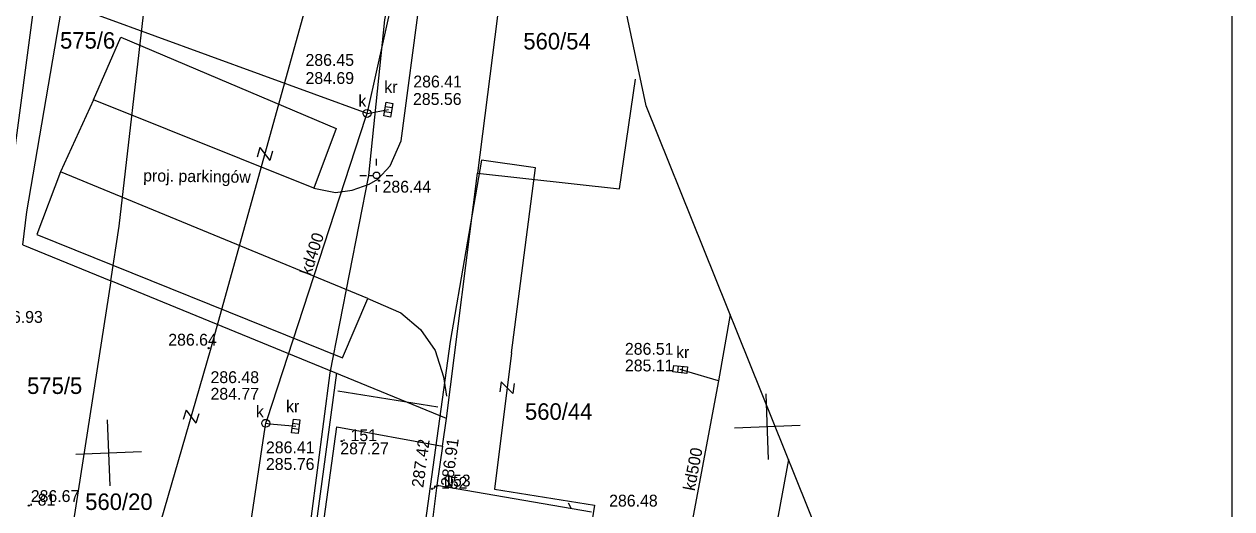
# Model space of a CAD drawing. Extents: x 4632591 to 4651936, y 5351032 to 5369988.
# Drawn here: x 4642775.6 to 4642867.2, y 5360195 to 5360231.7 of the extents above; entities that cross this region are included whole.
import ezdxf

# ---------------------------------------------------------------- set-up
doc = ezdxf.new("R2010")
doc.units = 0
for name, color, linetype in [('EBUPO_314', 7, 'Continuous'), ('EBUPP_312', 7, 'Continuous'), ('EDTTS_991', 7, 'Continuous'), ('EDZPD_211', 7, 'Continuous'), ('EDZPD_219', 7, 'Continuous'), ('SDRPK_420', 7, 'Continuous'), ('SDRPK_422', 7, 'Continuous'), ('SDRPK_432', 7, 'Continuous'), ('SDRPT_450', 7, 'Continuous'), ('UEEPA_510', 7, 'Continuous'), ('UEEPO_585', 7, 'Continuous'), ('UEETA_515', 7, 'Continuous'), ('UKKPA_506', 7, 'Continuous'), ('UKKPA_509', 7, 'Continuous'), ('UKKPO_582', 7, 'Continuous'), ('Warstwa 40', 7, 'Continuous'), ('Warstwa 50', 7, 'Continuous'), ('Warstwa 62', 7, 'Continuous'), ('WUKPS_403', 7, 'Continuous')]:
    doc.layers.add(name, color=color, linetype=linetype)

msp = doc.modelspace()

# ---------------------------------------------------------------- linework, layer by layer
at = {"layer": 'EBUPO_314'}
msp.add_line((4642773.082, 5360208.942), (4642777.949, 5360245.391), dxfattribs=at)
at = {"layer": 'EBUPP_312'}
msp.add_lwpolyline([(4642867.168, 5360325.869), (4642867.168, 5360025.339), (4642701.152, 5360025.339), (4642701.152, 5360349.707), (4642867.168, 5360349.707), (4642867.168, 5360324.166)], dxfattribs=at)
at = {"layer": 'EDTTS_991'}
for p, q in [((4642793.43, 5360222.392), (4642793.229, 5360221.669)), ((4642793.43, 5360222.392), (4642794.193, 5360221.402)), ((4642794.393, 5360222.124), (4642794.193, 5360221.402)), ((4642811.738, 5360204.618), (4642811.645, 5360203.874)), ((4642811.738, 5360204.618), (4642812.638, 5360203.751)), ((4642812.73, 5360204.495), (4642812.638, 5360203.751)), ((4642787.838, 5360202.488), (4642787.629, 5360201.768)), ((4642787.838, 5360202.488), (4642788.589, 5360201.489)), ((4642788.799, 5360202.209), (4642788.589, 5360201.489))]:
    msp.add_line(p, q, dxfattribs=at)
at = {"layer": 'EDZPD_219'}
for p, q in [((4642775.755, 5360217.52), (4642788.383, 5360291.17)), ((4642815.842, 5360266.866), (4642809.95, 5360220.44)), ((4642782.772, 5360216.437), (4642785.265, 5360238.119)), ((4642820.72, 5360219.25), (4642821.93, 5360227.578)), ((4642807.585, 5360201.84), (4642809.95, 5360220.44)), ((4642809.95, 5360220.44), (4642820.72, 5360219.25)), ((4642775.462, 5360215.022), (4642775.755, 5360217.52)), ((4642782.126, 5360212.287), (4642782.772, 5360216.437)), ((4642775.462, 5360215.022), (4642782.126, 5360212.287)), ((4642782.126, 5360212.287), (4642778.595, 5360189.601)), ((4642807.585, 5360201.84), (4642782.126, 5360212.287)), ((4642807.297, 5360199.758), (4642807.585, 5360201.84)), ((4642796.649, 5360182.126), (4642799.275, 5360201.211)), ((4642799.275, 5360201.211), (4642807.297, 5360199.758)), ((4642807.297, 5360199.758), (4642806.875, 5360196.789)), ((4642806.875, 5360196.789), (4642804.574, 5360178.838)), ((4642806.875, 5360196.789), (4642818.602, 5360194.772))]:
    msp.add_line(p, q, dxfattribs=at)
at = {"layer": 'SDRPK_420'}
msp.add_line((4642799.357, 5360203.945), (4642806.931, 5360202.734), dxfattribs=at)
msp.add_lwpolyline([(4642812.515, 5360206.822), (4642814.34, 5360220.838), (4642810.243, 5360221.424), (4642807.866, 5360207.685)], dxfattribs=at)
at = {"layer": 'SDRPK_422'}
for points in [[(4642800.957, 5360247.6), (4642789.673, 5360207.012), (4642785.643, 5360193.138), (4642783.61, 5360182.51), (4642781.64, 5360172.03), (4642777.96, 5360145.38), (4642775.66, 5360128.5)], [(4642812.515, 5360206.822), (4642811.234, 5360196.488), (4642818.833, 5360195.279), (4642818.488, 5360193.235), (4642816.156, 5360192.083), (4642814.63, 5360190.846), (4642812.385, 5360188.14), (4642811.608, 5360186.787), (4642811.061, 5360185.664), (4642810.572, 5360184.196), (4642810.14, 5360181.95), (4642810.054, 5360180.31), (4642810.313, 5360178.18), (4642810.543, 5360176.654), (4642811.003, 5360174.668), (4642811.406, 5360173.258), (4642811.694, 5360172.308), (4642810.888, 5360169.861), (4642808.456, 5360149.337), (4642812.07, 5360146.81), (4642807.12, 5360140.16), (4642810.67, 5360137.59), (4642805.721, 5360131.374)]]:
    msp.add_lwpolyline(points, dxfattribs=at)
at = {"layer": 'SDRPT_450'}
msp.add_line((4642784.66, 5360097.25), (4642799.288, 5360205.296), dxfattribs=at)
msp.add_lwpolyline([(4642807.866, 5360207.685), (4642795.027, 5360114.592), (4642791.918, 5360092.139)], dxfattribs=at)
at = {"layer": 'UEEPA_510'}
msp.add_circle((4642802.281, 5360220.279), 0.25, dxfattribs=at)
at = {"layer": 'UEEPO_585'}
for points in [[(4642801.706, 5360220.279), (4642802.915, 5360232.081), (4642806.657, 5360251.253)], [(4642796.855, 5360190.558), (4642798.769, 5360205.311), (4642801.706, 5360220.279), (4642802.031, 5360220.279)]]:
    msp.add_lwpolyline(points, dxfattribs=at)
at = {"layer": 'UEETA_515'}
for p, q in [((4642802.281, 5360221.029), (4642802.281, 5360221.529)), ((4642801.031, 5360220.279), (4642801.531, 5360220.279)), ((4642803.031, 5360220.279), (4642803.531, 5360220.279)), ((4642802.281, 5360219.029), (4642802.281, 5360219.529)), ((4642816.826, 5360195.456), (4642817.065, 5360195.017))]:
    msp.add_line(p, q, dxfattribs=at)
at = {"layer": 'UKKPA_506'}
for centre in [(4642801.576, 5360224.971), (4642793.89, 5360201.482)]:
    msp.add_circle(centre, 0.3, dxfattribs=at)
at = {"layer": 'UKKPA_509'}
for p, q in [((4642803.463, 5360225.391), (4642802.97, 5360225.473)), ((4642802.913, 5360225.127), (4642803.406, 5360225.045)), ((4642825.178, 5360205.837), (4642825.123, 5360205.341)), ((4642825.47, 5360205.302), (4642825.526, 5360205.799)), ((4642795.895, 5360201.109), (4642796.391, 5360201.047)), ((4642796.434, 5360201.394), (4642795.938, 5360201.456))]:
    msp.add_line(p, q, dxfattribs=at)
for points in [[(4642802.855, 5360224.782), (4642803.028, 5360225.818), (4642803.521, 5360225.736), (4642803.349, 5360224.7)], [(4642824.83, 5360205.876), (4642825.874, 5360205.76), (4642825.818, 5360205.263), (4642824.775, 5360205.379)], [(4642795.851, 5360200.762), (4642795.982, 5360201.804), (4642796.478, 5360201.742), (4642796.347, 5360200.7)]]:
    msp.add_lwpolyline(points, close=True, dxfattribs=at)
at = {"layer": 'UKKPO_582'}
for p, q in [((4642801.645, 5360225.263), (4642807.389, 5360250.973)), ((4642801.576, 5360224.971), (4642801.645, 5360225.263))]:
    msp.add_line(p, q, dxfattribs=at)
for points in [[(4642793.984, 5360201.767), (4642801.483, 5360224.686)], [(4642801.483, 5360224.686), (4642801.576, 5360224.971), (4642801.871, 5360225.024)], [(4642801.871, 5360225.024), (4642802.927, 5360225.212)], [(4642802.927, 5360225.212), (4642803.188, 5360225.259)], [(4642829.119, 5360209.728), (4642828.232, 5360204.706), (4642825.836, 5360205.418)], [(4642825.836, 5360205.418), (4642825.324, 5360205.57)], [(4642828.232, 5360204.706), (4642825.841, 5360192.047)], [(4642793.89, 5360201.482), (4642793.984, 5360201.767)], [(4642788.753, 5360167.207), (4642793.846, 5360201.186)], [(4642793.846, 5360201.186), (4642793.89, 5360201.482), (4642794.187, 5360201.452)], [(4642794.187, 5360201.452), (4642795.916, 5360201.277)], [(4642795.916, 5360201.277), (4642796.164, 5360201.252)], [(4642833.551, 5360198.727), (4642828.199, 5360169.831)]]:
    msp.add_lwpolyline(points, dxfattribs=at)
at = {"layer": 'Warstwa 40'}
for p, q in [((4642822.748, 5360225.547), (4642809.351, 5360288.674)), ((4642804.154, 5360222.901), (4642805.723, 5360234.66)), ((4642801.576, 5360224.971), (4642776.963, 5360233.955)), ((4642780.821, 5360226.014), (4642782.896, 5360230.749)), ((4642782.896, 5360230.749), (4642799.232, 5360223.832)), ((4642780.821, 5360226.014), (4642778.32, 5360220.533)), ((4642797.529, 5360219.309), (4642780.821, 5360226.014)), ((4642843.767, 5360173.362), (4642822.748, 5360225.547)), ((4642799.232, 5360223.832), (4642797.529, 5360219.309)), ((4642803.329, 5360221.012), (4642804.154, 5360222.901)), ((4642802.398, 5360220.001), (4642803.329, 5360221.012)), ((4642778.32, 5360220.533), (4642776.511, 5360215.797)), ((4642801.626, 5360210.955), (4642778.32, 5360220.533)), ((4642801.733, 5360219.602), (4642802.398, 5360220.001)), ((4642797.529, 5360219.309), (4642799.178, 5360218.99)), ((4642799.178, 5360218.99), (4642800.429, 5360219.15)), ((4642800.429, 5360219.15), (4642801.733, 5360219.602)), ((4642776.511, 5360215.797), (4642799.711, 5360206.432)), ((4642799.711, 5360206.432), (4642801.626, 5360210.955)), ((4642801.626, 5360210.955), (4642804.127, 5360209.865)), ((4642804.127, 5360209.865), (4642805.617, 5360208.587)), ((4642805.617, 5360208.587), (4642806.734, 5360206.991)), ((4642806.734, 5360206.991), (4642807.373, 5360204.996)), ((4642807.373, 5360204.996), (4642807.586, 5360203.533))]:
    msp.add_line(p, q, dxfattribs=at)
at = {"layer": 'Warstwa 50'}
for p, q in [((4642832.034, 5360198.732), (4642831.837, 5360203.728)), ((4642782.074, 5360196.753), (4642781.876, 5360201.749)), ((4642829.437, 5360201.131), (4642834.434, 5360201.329)), ((4642779.477, 5360199.152), (4642784.473, 5360199.35))]:
    msp.add_line(p, q, dxfattribs=at)
at = {"layer": 'WUKPS_403'}
for centre in [(4642802.481, 5360219.871), (4642789.551, 5360207.181), (4642799.65, 5360200.13), (4642806.51, 5360196.52), (4642806.75, 5360196.69), (4642775.92, 5360195.24)]:
    msp.add_circle(centre, 0.045, dxfattribs=at)

# ---------------------------------------------------------------- texts
at = {"layer": 'EDZPD_211'}
for s, p in [('575/6', (4642778.284, 5360229.885)), ('560/54', (4642813.425, 5360229.825)), ('575/5', (4642775.784, 5360203.706)), ('560/44', (4642813.551, 5360201.748)), ('560/20', (4642780.191, 5360194.911))]:
    msp.add_text(s, height=1.25, dxfattribs=at).set_placement(p)
at = {"layer": 'SDRPK_432'}
msp.add_text('proj. parkingów', height=0.9, rotation=359.18617, dxfattribs=at).set_placement((4642784.584, 5360219.822))
at = {"layer": 'UKKPA_506'}
for s, p in [('286.45', (4642796.902, 5360228.577)), ('284.69', (4642796.902, 5360227.207)), ('kr', (4642802.879, 5360226.534)), ('k', (4642800.914, 5360225.475)), ('kr', (4642825.014, 5360206.421)), ('286.48', (4642789.697, 5360204.527)), ('284.77', (4642789.697, 5360203.267)), ('k', (4642793.142, 5360201.928)), ('kr', (4642795.429, 5360202.324))]:
    msp.add_text(s, height=0.9, dxfattribs=at).set_placement(p)
at = {"layer": 'UKKPA_509'}
for s, p in [('286.41', (4642805.079, 5360226.941)), ('285.56', (4642805.057, 5360225.615)), ('286.51', (4642821.131, 5360206.675)), ('285.11', (4642821.131, 5360205.415)), ('286.41', (4642793.901, 5360199.206)), ('285.76', (4642793.901, 5360197.946)), ('286.48', (4642819.934, 5360195.169))]:
    msp.add_text(s, height=0.9, dxfattribs=at).set_placement(p)
at = {"layer": 'UKKPO_582'}
for s, rotation, p in [('kd400', 71.88308, (4642797.302, 5360212.63)), ('kd500', 79.30003, (4642826.419, 5360196.318))]:
    msp.add_text(s, height=0.9, rotation=rotation, dxfattribs=at).set_placement(p)
at = {"layer": 'Warstwa 62'}
for s, p in [('. 151', (4642799.65, 5360200.13)), ('. 152', (4642806.51, 5360196.52)), ('. 153', (4642806.75, 5360196.69)), ('. 81', (4642775.92, 5360195.24))]:
    msp.add_text(s, height=0.9, dxfattribs=at).set_placement(p)
at = {"layer": 'WUKPS_403'}
for s, p in [('286.44', (4642802.747, 5360218.967)), ('286.93', (4642773.295, 5360209.096)), ('286.64', (4642786.491, 5360207.367)), ('287.27', (4642799.541, 5360199.126)), ('286.67', (4642776.062, 5360195.514))]:
    msp.add_text(s, height=0.9, dxfattribs=at).set_placement(p)
for s, p in [('287.42', (4642805.833, 5360196.565)), ('286.91', (4642808.041, 5360196.645))]:
    msp.add_text(s, height=0.9, rotation=82.28998, dxfattribs=at).set_placement(p)

doc.saveas('drawing.dxf')
